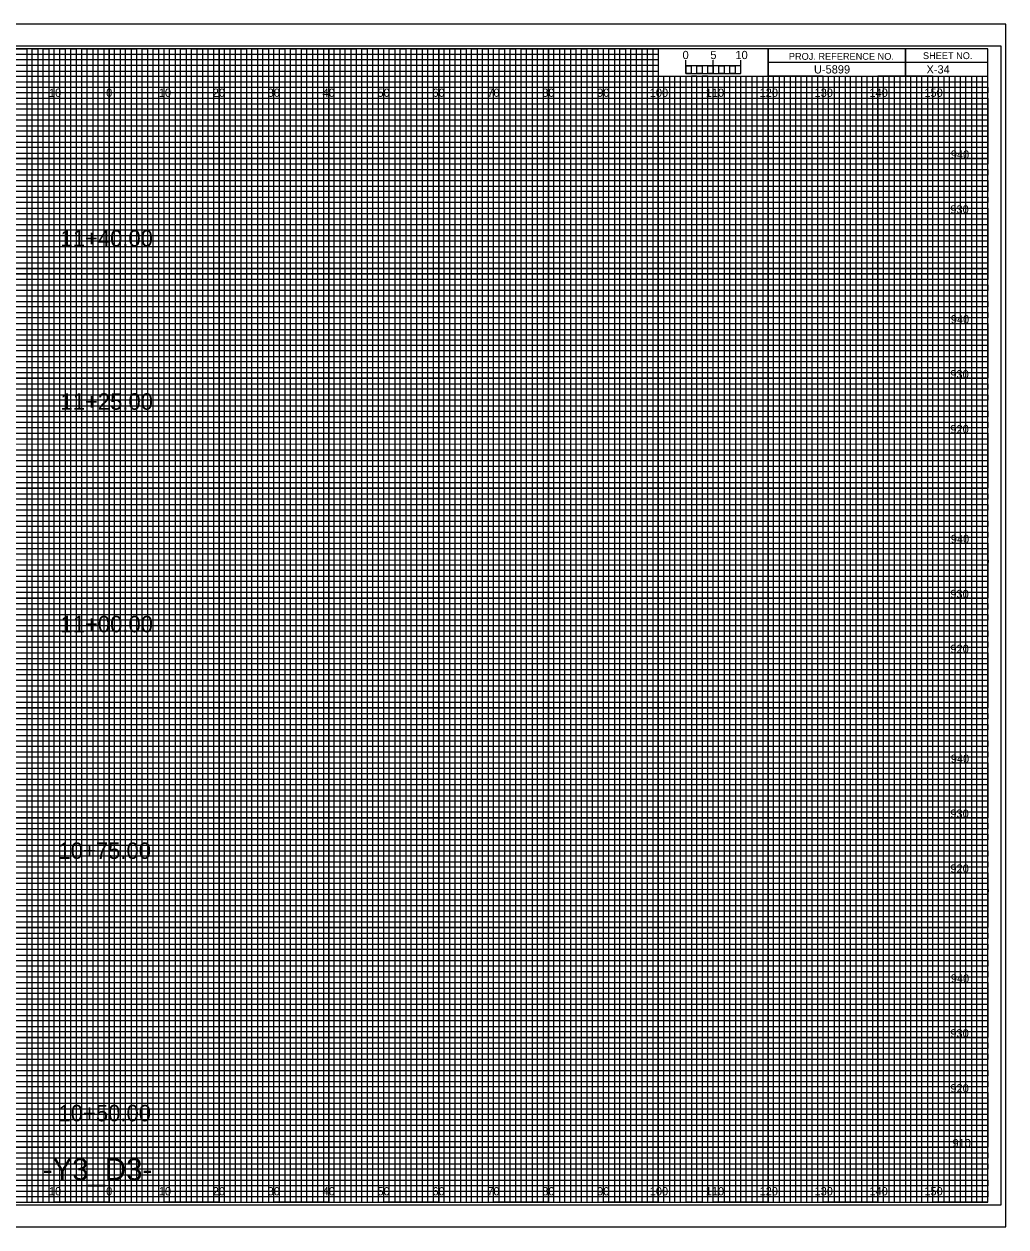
# Model space of a CAD drawing. Extents: x -13 to 323, y -4 to 214.
# Drawn here: x 144.5 to 323.3, y -4.5 to 214.5 of the extents above; entities that cross this region are included whole.
import ezdxf

# ---------------------------------------------------------------- set-up
doc = ezdxf.new("R2010")
doc.units = 0
for name, color, linetype in [('Prop XS Alignment Label', 7, 'Continuous'), ('Prop XS Bar Scale Labels', 7, 'Continuous'), ('Prop XS Elevation Labels', 7, 'Continuous'), ('Prop XS Offset Labels', 7, 'Continuous'), ('Prop XS Project Number', 7, 'Continuous'), ('Prop XS Sheet Number', 7, 'Continuous'), ('Prop XS Station Labels', 7, 'Continuous'), ('Sheet Cross Section CELL', 7, 'Continuous'), ('Sheet Cross Section Grid Major CELL', 7, 'Continuous'), ('Sheet Cross Section Grid Middle CELL', 7, 'Continuous'), ('Sheet Cross Section Grid Minor 1 CELL', 7, 'Continuous'), ('Sheet Cross Section Grid Minor 2 CELL', 7, 'Continuous'), ('Sheet Cross Section Scale CELL', 7, 'Continuous'), ('Sheet Cutting Line CELL', 7, 'Continuous'), ('Sheet DOT Grid CELL', 7, 'Continuous'), ('Sheet Plot Border Inside CELL', 7, 'Continuous'), ('Sheet Plot Border Outside CELL', 7, 'Continuous')]:
    doc.layers.add(name, color=color, linetype=linetype)

msp = doc.modelspace()

# ---------------------------------------------------------------- linework, layer by layer
at = {"layer": 'Sheet Cross Section CELL'}
for p, q in [((305, 210), (305, 205)), ((305, 205), (305, 210)), ((280, 207.5), (280, 205)), ((320, 207.49), (280, 207.49)), ((280, 205), (320, 205))]:
    msp.add_line(p, q, dxfattribs=at)
for points in [[(320, 210), (0, 210), (0, 0), (320, 0)], [(280, 210), (260, 210), (260, 205.03), (280, 205.03)], [(320, 210), (280, 210), (280, 205), (320, 205)]]:
    msp.add_lwpolyline(points, close=True, dxfattribs=at)
at = {"layer": 'Sheet Cross Section Grid Major CELL'}
for p, q in [((150, 210), (140, 210)), ((150, 0), (150, 210)), ((170, 210), (160, 210)), ((160, 210), (160, 0)), ((170, 0), (170, 210)), ((190, 210), (180, 210)), ((180, 210), (180, 0)), ((190, 0), (190, 210)), ((210, 210), (200, 210)), ((200, 210), (200, 0)), ((210, 0), (210, 210)), ((230, 210), (220, 210)), ((220, 210), (220, 0)), ((230, 0), (230, 210)), ((250, 210), (240, 210)), ((240, 210), (240, 0)), ((250, 0), (250, 210)), ((260, 210), (260, 0)), ((270, 0), (270, 205)), ((290, 205), (280, 205)), ((280, 205), (280, 0)), ((290, 0), (290, 205)), ((310, 205), (300, 205)), ((300, 205), (300, 0)), ((310, 0), (310, 205)), ((160, 0), (150, 0)), ((180, 0), (170, 0)), ((200, 0), (190, 0)), ((220, 0), (210, 0)), ((240, 0), (230, 0)), ((260, 0), (250, 0)), ((280, 0), (270, 0)), ((300, 0), (290, 0)), ((320, 0), (310, 0)), ((320, 0), (320, 0))]:
    msp.add_line(p, q, dxfattribs=at)
for points in [[(0, 200), (320, 200), (320, 190), (0, 190)], [(0, 180), (320, 180), (320, 170), (0, 170)], [(0, 160), (320, 160), (320, 150), (0, 150)], [(0, 140), (320, 140), (320, 130), (0, 130)], [(0, 120), (320, 120), (320, 110), (0, 110)], [(0, 100), (320, 100), (320, 90), (0, 90)], [(0, 80), (320, 80), (320, 70), (0, 70)], [(0, 60), (320, 60), (320, 50), (0, 50)], [(0, 40), (320, 40), (320, 30), (0, 30)], [(0, 20), (320, 20), (320, 10), (0, 10)]]:
    msp.add_lwpolyline(points, dxfattribs=at)
at = {"layer": 'Sheet Cross Section Grid Middle CELL'}
for points in [[(135, 210), (145, 210), (145, 0), (155, 0), (155, 210), (165, 210), (165, 0), (175, 0), (175, 210), (185, 210), (185, 0), (195, 0), (195, 210), (205, 210), (205, 0), (215, 0), (215, 210), (225, 210), (225, 0), (235, 0), (235, 210), (245, 210), (245, 0), (255, 0), (255, 210), (259.93, 210), (260, 210), (260, 205), (264.99, 205), (264.99, 0), (275, 0), (275, 205), (285, 205), (285, 0), (295, 0), (295, 205), (305, 205), (305, 0), (315, 0), (315, 205)], [(0, 205), (275, 205)], [(0, 185), (320, 185), (320, 195), (0, 195)], [(0, 165), (320, 165), (320, 175), (0, 175)], [(0, 145), (320, 145), (320, 155), (0, 155)], [(0, 125), (320, 125), (320, 135), (0, 135)], [(0, 105), (320, 105), (320, 115), (0, 115)], [(0, 85), (320, 85), (320, 95), (0, 95)], [(0, 65), (320, 65), (320, 75), (0, 75)], [(0, 45), (320, 45), (320, 55), (0, 55)], [(0, 25), (320, 25), (320, 35), (0, 35)], [(0, 5), (320, 5), (320, 15), (0, 15)]]:
    msp.add_lwpolyline(points, dxfattribs=at)
at = {"layer": 'Sheet Cross Section Grid Minor 1 CELL'}
for p, q in [((0, 209), (260, 209)), ((260, 209), (260, 207.98)), ((260, 207.98), (0, 207.98)), ((0, 207), (260, 207)), ((260, 205.89), (0, 205.89)), ((260, 207), (260, 205.89)), ((0, 204), (320, 204))]:
    msp.add_line(p, q, dxfattribs=at)
for points in [[(0, 203), (270, 203), (320, 203), (320, 202), (0, 202)], [(0, 201), (320, 201), (320, 199), (0, 199)], [(0, 198), (320, 198), (320, 197), (0, 196.98)], [(0, 196), (320, 196), (320, 194), (0, 194)], [(0, 193), (320, 193), (320, 192), (0, 192)], [(0, 191), (320, 191), (320, 189), (0, 189)], [(0, 188), (320, 188), (320, 187), (0, 187)], [(0, 186), (320, 186), (320, 184), (0, 184)], [(0, 183), (320, 183), (320, 182), (0, 182)], [(0, 181), (320, 181), (320, 179), (0, 179)], [(0, 178), (320, 178), (320, 177), (0, 177)], [(0, 176), (320, 176), (320, 173.95), (320, 173), (320, 172), (0, 172)], [(0, 174), (320, 174), (320, 173), (0, 173)], [(0, 171), (320, 171), (320, 169), (0, 169.03)], [(0, 169.03), (320, 169), (320, 168), (0, 168)], [(0, 167), (320, 167), (320, 166), (0, 166)], [(0, 164), (320, 164), (320, 163), (0, 163)], [(0, 162), (320, 162), (320, 161), (0, 161)], [(-0.07, 158.89), (320, 158.89), (320, 157.88), (-0.07, 157.88)], [(0, 157), (320, 157), (320, 156), (0, 156)], [(0, 154), (320, 154), (320, 153), (0, 153)], [(0, 152), (320, 152), (320, 151), (0, 151)], [(0, 149), (320, 149), (320, 148), (0, 148)], [(0, 147), (320, 147), (320, 146), (0, 146)], [(0, 144), (320, 144), (320, 143), (0, 143)], [(0, 142), (320, 142), (320, 141), (0, 141)], [(0, 139), (320, 139), (319.99, 137.98), (0, 138)], [(0, 137), (320, 137), (320, 136), (0, 136)], [(0, 134), (320, 134), (320, 133), (0, 133)], [(0, 132), (320, 132), (320, 131), (0, 131)], [(0, 129), (320, 129), (320, 128), (0, 128)], [(0, 127), (320, 127), (320, 126), (0, 126)], [(0, 124), (320, 124), (320, 123), (0, 123)], [(0, 122), (320, 122), (320, 121), (0, 121)], [(0, 119), (320, 119), (320, 118), (0, 118)], [(0, 116.99), (320.07, 116.91), (320, 116), (0, 116)], [(0, 114), (320, 114), (320, 113), (0, 113)], [(0, 112), (320, 112), (320, 111), (0, 111)], [(0, 109), (320, 109), (320, 108), (0, 108)], [(0, 107), (320, 107), (320, 106), (0, 106)], [(0, 104), (320, 104), (320, 103), (0, 103)], [(0, 102), (320, 102), (320, 101), (0, 101)], [(0, 99), (320, 99), (320, 98), (0, 98)], [(0, 97), (320, 97), (320, 96), (0, 96)], [(0, 94), (320, 94), (320, 93), (0, 93)], [(0, 92), (320, 92), (320, 91), (0, 91)], [(0, 89), (320, 89), (320, 88), (0, 88)], [(0, 87), (320, 87), (320, 86), (0, 86)], [(0, 84), (320, 84), (320, 83), (0, 83)], [(0, 82), (320, 82), (320, 81), (0, 81)], [(0, 79), (320, 79), (319.99, 77.98), (0, 78)], [(0, 77), (320, 77), (320, 76), (0, 76)], [(0, 74), (320, 74), (320, 73), (0, 73)], [(0, 72), (320, 72), (320, 71), (0, 71)], [(0, 69), (320, 69), (320, 68), (0, 68)], [(0, 67), (320, 67), (320, 66), (0, 66)], [(0, 64), (320, 64), (320, 63), (0, 63)], [(0, 62), (320, 62), (320, 61), (0, 61)], [(0, 59), (320, 59), (320, 58), (0, 58)], [(0, 56.99), (320.07, 56.91), (320, 56), (0, 56)], [(0, 54), (320, 54), (320, 53), (0, 53)], [(0, 52), (320, 52), (320, 51), (0, 51)], [(0, 49), (320, 49), (320, 48), (0, 48)], [(0, 47), (320, 47), (320, 46), (0, 46)], [(0, 44), (320, 44), (320, 43), (0, 43)], [(0, 42), (320, 42), (320, 41), (0, 41)], [(0, 39), (320, 39), (320, 38), (0, 38)], [(0, 37), (320, 37), (320, 36), (0, 36)], [(0, 34), (320, 34), (320, 33), (0, 33)], [(0, 32), (320, 32), (320, 31), (0, 31)], [(0, 29), (320, 29), (320, 28), (0, 28)], [(0, 27), (320, 27), (320, 26), (0, 26)], [(0, 24), (320, 24), (320, 23), (0, 23)], [(0, 22), (320, 22), (320, 21), (0, 21)], [(0, 19), (320, 19), (320, 18), (0, 18)], [(0, 17), (320, 17), (320, 16), (0, 16)], [(0, 14), (320, 14), (320, 13), (0, 13)], [(0, 12), (320, 12), (320, 11), (0, 11)], [(0, 9), (320, 9), (320, 8), (0, 8)], [(0, 7), (320, 7), (320, 6), (0, 6)], [(0, 4), (320, 4), (320, 3), (0, 3)], [(0, 2), (320, 2), (320, 1), (0, 1)]]:
    msp.add_lwpolyline(points, dxfattribs=at)
at = {"layer": 'Sheet Cross Section Grid Minor 2 CELL'}
for p, q in [((267, 205), (266.01, 205)), ((266.01, 205), (266.01, 0)), ((267, 0), (267, 205)), ((269, 205), (268, 205)), ((268, 205), (268, 0)), ((269, 0), (269, 205)), ((266.01, 0), (265, 0)), ((268, 0), (267, 0))]:
    msp.add_line(p, q, dxfattribs=at)
for points in [[(145, 0), (146, 0), (146, 210), (147, 210), (147, 0)], [(147, 0), (148, 0), (148, 210), (149, 210), (149, 0)], [(150, 0), (151, 0), (151, 210), (152, 210), (152, 0)], [(152, 0), (153, 0), (153, 210), (154, 210), (154, 0)], [(155, 0), (156, 0), (156, 210), (157, 210), (157, 0)], [(157, 0), (158, 0), (158, 210), (159, 210), (159, 0)], [(160, 0), (161, 0), (161, 210), (162, 210), (162, 0)], [(162, 0), (163, 0), (163, 210), (164, 210), (164, 0)], [(165, 0), (166, 0), (166, 210), (167, 210), (167, 0)], [(167, 0), (168, 0), (168, 210), (169, 210), (169, 0)], [(170, 0), (171, 0), (171, 210), (172, 210), (172, 0)], [(172, 0), (173, 0), (173, 210), (174, 210), (174, 0)], [(175, 0), (176, 0), (176, 210), (177, 210), (177, 0)], [(177, 0), (178, 0), (178, 210), (179, 210), (179, 0)], [(180, 0), (181, 0), (181, 210), (182, 210), (182, 0)], [(182, 0), (183, 0), (183, 210), (184, 210), (184, 0)], [(185, 0), (186, 0), (186, 210), (187, 210), (187, 0)], [(187, 0), (188, 0), (188, 210), (189, 210), (189, 0)], [(190, 0), (191, 0), (191, 210), (192, 210), (192, 0)], [(192, 0), (193, 0), (193, 210), (194, 210), (194, 0)], [(195, 0), (196, 0), (196, 210), (197, 210), (197, 0)], [(197, 0), (198, 0), (198, 210), (199, 210), (199, 0)], [(200, 0), (201, 0), (201, 210), (202, 210), (202, 0)], [(202, 0), (203, 0), (203, 210), (204, 210), (204, 0)], [(205, 0), (206, 0), (206, 210), (207, 210), (207, 0)], [(207, 0), (208, 0), (208, 210), (209, 210), (209, 0)], [(210, 0), (211, 0), (211, 210), (212, 210), (212, 0)], [(212, 0), (213, 0), (213, 210), (214, 210), (214, 0)], [(215, 0), (216, 0), (216, 210), (217, 210), (217, 0)], [(217, 0), (218, 0), (218, 210), (219, 210), (219, 0)], [(220, 0), (221, 0), (221, 210), (222, 210), (222, 0)], [(222, 0), (223, 0), (223, 210), (224, 210), (224, 0)], [(225, 0), (226, 0), (226, 210), (227, 210), (227, 0)], [(227, 0), (228, 0), (228, 210), (229, 210), (229, 0)], [(230, 0), (231, 0), (231, 210), (232, 210), (232, 0)], [(232, 0), (233, 0), (233, 210), (234, 210), (234, 0)], [(235, 0), (236, 0), (236, 210), (237, 210), (237, 0)], [(237, 0), (238, 0), (238, 210), (239, 210), (239, 0)], [(240, 0), (241, 0), (241, 210), (242, 210), (242, 0)], [(242, 0), (243, 0), (243, 210), (244, 210), (244, 0)], [(245, 0), (246, 0), (246, 210), (247, 210), (247, 0)], [(247, 0), (248, 0), (248, 210), (249, 210), (249, 0)], [(250, 0), (251, 0), (251, 210), (252, 210), (252, 0)], [(252, 0), (253, 0), (253, 210), (254, 210), (254, 0)], [(255, 0), (256, 0), (256, 210), (257, 210), (257, 0)], [(257, 0), (258, 0), (258, 210), (259, 210), (259, 0)], [(260, 0), (261, 0), (261, 205), (262.02, 205), (262.02, 0)], [(262, 0), (263, 0), (263, 205), (263.99, 205), (263.99, 0)], [(270, 0), (270.98, 0), (270.98, 205), (272, 205), (272, 0)], [(272, 0), (273, 0), (273, 205), (274.05, 205), (274.05, 0)], [(275, 0), (276, 0), (276, 205), (277, 205), (277, 0)], [(277, 0), (278, 0), (278, 205), (279, 205), (279, 0)], [(280, 0), (281, 0), (281, 205), (282, 205), (282, 0)], [(282, 0), (283, 0), (283, 205), (284, 205), (284, 0)], [(285, 0), (286, 0), (286, 205), (287, 205), (287, 0)], [(287, 0), (288, 0), (288, 205), (289, 205), (289, 0)], [(290, 0), (291, 0), (291, 205), (292, 205), (292, 0)], [(292, 0), (293, 0), (293, 205), (294, 205), (294, 0)], [(295, 0), (296, 0), (296, 205), (297, 205), (297, 0)], [(297, 0), (298, 0), (298, 205), (299, 205), (299, 0)], [(300, 0), (301, 0), (301, 205), (302, 205), (302, 0)], [(302, 0), (303, 0), (303, 205), (304, 205), (304, 0)], [(305, 0), (306, 0), (306, 205), (307, 205), (307, 0)], [(307, 0), (308, 0), (308, 205), (309, 205), (309, 0)], [(310, 0), (311, 0), (311, 205), (312, 205), (312, 0)], [(312, 0), (313, 0), (313, 205), (314, 205), (314, 0)], [(315, 0), (316, 0), (316, 205), (317, 205), (317, 0)], [(317, 0), (318, 0), (318, 205), (319, 205), (319, 0)]]:
    msp.add_lwpolyline(points, dxfattribs=at)
at = {"layer": 'Sheet Cross Section Scale CELL'}
for p, q in [((265, 205.49), (265, 207.9)), ((265, 206.9), (265, 207.9)), ((270, 205.49), (270, 207.9)), ((275, 205.49), (275, 207.9)), ((275, 206.9), (275, 207.9))]:
    msp.add_line(p, q, dxfattribs=at)
for points in [[(275, 206.9), (265, 206.9), (265, 205.49), (275, 205.49)], [(265, 206.9), (266, 206.9), (266, 205.49), (265, 205.49)], [(267, 206.9), (268, 206.9), (268, 205.49), (267, 205.49)], [(269, 206.9), (270, 206.9), (270, 205.49), (269, 205.49)], [(271, 206.9), (272, 206.9), (272, 205.49), (271, 205.49)], [(273, 206.9), (274, 206.9), (274, 205.49), (273, 205.49)]]:
    msp.add_lwpolyline(points, close=True, dxfattribs=at)
at = {"layer": 'Sheet Cutting Line CELL'}
for p, q in [((323.3, 214.5), (-13.4, 214.5)), ((-13.4, -4.5), (323.3, -4.5))]:
    msp.add_line(p, q, dxfattribs=at)
at = {"layer": 'Sheet DOT Grid CELL'}
for p, q in [((150, 0), (150, 210)), ((160, 0), (160, 210)), ((170, 0), (170, 210)), ((180, 0), (180, 210)), ((190, 0), (190, 210)), ((200, 0), (200, 210)), ((210, 0), (210, 210)), ((220, 0), (220, 210)), ((230, 0), (230, 210)), ((240, 0), (240, 210)), ((250, 0), (250, 210)), ((260, 0), (260, 204.69)), ((270, 0), (270, 204.69)), ((280, 0), (280, 204.69)), ((290, 0), (290, 204.69)), ((300, 0), (300, 204.69)), ((310, 0), (310, 204.69)), ((0, 200), (320, 200)), ((0, 190), (320, 190)), ((0, 180), (320, 180)), ((0, 170), (320, 170)), ((0, 160), (320, 160)), ((0, 150), (320, 150)), ((0, 140), (320, 140)), ((0, 130), (320, 130)), ((0, 120), (320, 120)), ((0, 110), (320, 110)), ((0, 100), (320, 100)), ((0, 90), (320, 90)), ((0, 80), (320, 80)), ((0, 70), (320, 70)), ((0, 60), (320, 60)), ((0, 50), (320, 50)), ((0, 40), (320, 40)), ((0, 30), (320, 30)), ((0, 20), (320, 20)), ((0, 10), (320, 10))]:
    msp.add_line(p, q, dxfattribs=at)
at = {"layer": 'Sheet Plot Border Inside CELL'}
msp.add_lwpolyline([(-10.8, -0.5), (322.4, -0.5), (322.4, 210.5), (-10.8, 210.5)], close=True, dxfattribs=at)
at = {"layer": 'Sheet Plot Border Outside CELL'}
msp.add_lwpolyline([(-13.4, -4.5), (323.3, -4.5), (323.3, 214.5), (-13.4, 214.5)], close=True, dxfattribs=at)

# ---------------------------------------------------------------- texts
at = {"layer": 'Prop XS Alignment Label'}
msp.add_text('-Y3_D3-', height=4, dxfattribs=at).set_placement((147.92, 4))
at = {"layer": 'Prop XS Bar Scale Labels'}
for s, p in [('5', (269.47, 208.12)), ('10', (274.04, 208.12))]:
    msp.add_text(s, height=1.5, dxfattribs=at).set_placement(p)
at = {"layer": 'Prop XS Elevation Labels'}
for s, p in [('940', (313.26, 190)), ('930', (313.18, 180)), ('940', (313.26, 160)), ('930', (313.18, 150)), ('920', (313.19, 140)), ('940', (313.26, 120)), ('930', (313.18, 110)), ('920', (313.19, 100)), ('940', (313.26, 80)), ('930', (313.18, 70)), ('920', (313.19, 60)), ('940', (313.26, 40)), ('930', (313.18, 30)), ('920', (313.19, 20)), ('910', (313.57, 10))]:
    msp.add_text(s, height=1.5, dxfattribs=at).set_placement(p)
at = {"layer": 'Prop XS Offset Labels'}
for s, p in [('10', (149.04, 201.25)), ('0', (159.45, 201.25)), ('0', (159.45, 201.25)), ('10', (169.04, 201.25)), ('20', (178.86, 201.25)), ('30', (188.86, 201.25)), ('40', (198.86, 201.25)), ('50', (208.86, 201.25)), ('60', (218.86, 201.25)), ('70', (228.86, 201.25)), ('80', (238.86, 201.25)), ('90', (248.86, 201.25)), ('100', (258.44, 201.25)), ('110', (268.62, 201.25)), ('120', (278.44, 201.25)), ('130', (288.44, 201.25)), ('140', (298.44, 201.25)), ('150', (308.44, 201.25)), ('10', (149.04, 1.25)), ('0', (159.45, 1.25)), ('0', (159.45, 1.25)), ('10', (169.04, 1.25)), ('20', (178.86, 1.25)), ('30', (188.86, 1.25)), ('40', (198.86, 1.25)), ('50', (208.86, 1.25)), ('60', (218.86, 1.25)), ('70', (228.86, 1.25)), ('80', (238.86, 1.25)), ('90', (248.86, 1.25)), ('100', (258.44, 1.25)), ('110', (268.62, 1.25)), ('120', (278.44, 1.25)), ('130', (288.44, 1.25)), ('140', (298.44, 1.25)), ('150', (308.44, 1.25))]:
    msp.add_text(s, height=1.5, dxfattribs=at).set_placement(p)
at = {"layer": 'Prop XS Project Number'}
msp.add_text('U-5899', height=1.5, dxfattribs=at).set_placement((288.34, 205.5))
at = {"layer": 'Prop XS Sheet Number'}
msp.add_text('X-34', height=1.5, dxfattribs=at).set_placement((308.83, 205.5))
at = {"layer": 'Prop XS Station Labels'}
for s, p in [('11+40.00', (151.13, 174)), ('11+25.00', (151.13, 144.28)), ('11+00.00', (151.13, 103.76)), ('10+75.00', (150.77, 62.51)), ('10+50.00', (150.77, 14.73))]:
    msp.add_text(s, height=3, dxfattribs=at).set_placement(p)
at = {"layer": 'Sheet Cross Section CELL'}
for s, p in [('PROJ. REFERENCE NO.', (283.77, 207.99)), ('SHEET NO.', (308.19, 208.12))]:
    msp.add_text(s, height=1.25, dxfattribs=at).set_placement(p)
at = {"layer": 'Sheet Cross Section Scale CELL'}
msp.add_text('0', height=1.5, dxfattribs=at).set_placement((264.41, 208.12))

doc.saveas('drawing.dxf')
